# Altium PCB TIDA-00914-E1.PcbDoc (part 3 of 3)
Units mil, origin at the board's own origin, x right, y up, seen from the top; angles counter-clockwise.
Board outline 6575 x 7007.88 mil, 4 copper layers (Top Layer, GND, PWR, Bottom Layer), stack 79.834 mil thick; 302 components, 122 nets, 688 pads, 184 vias.
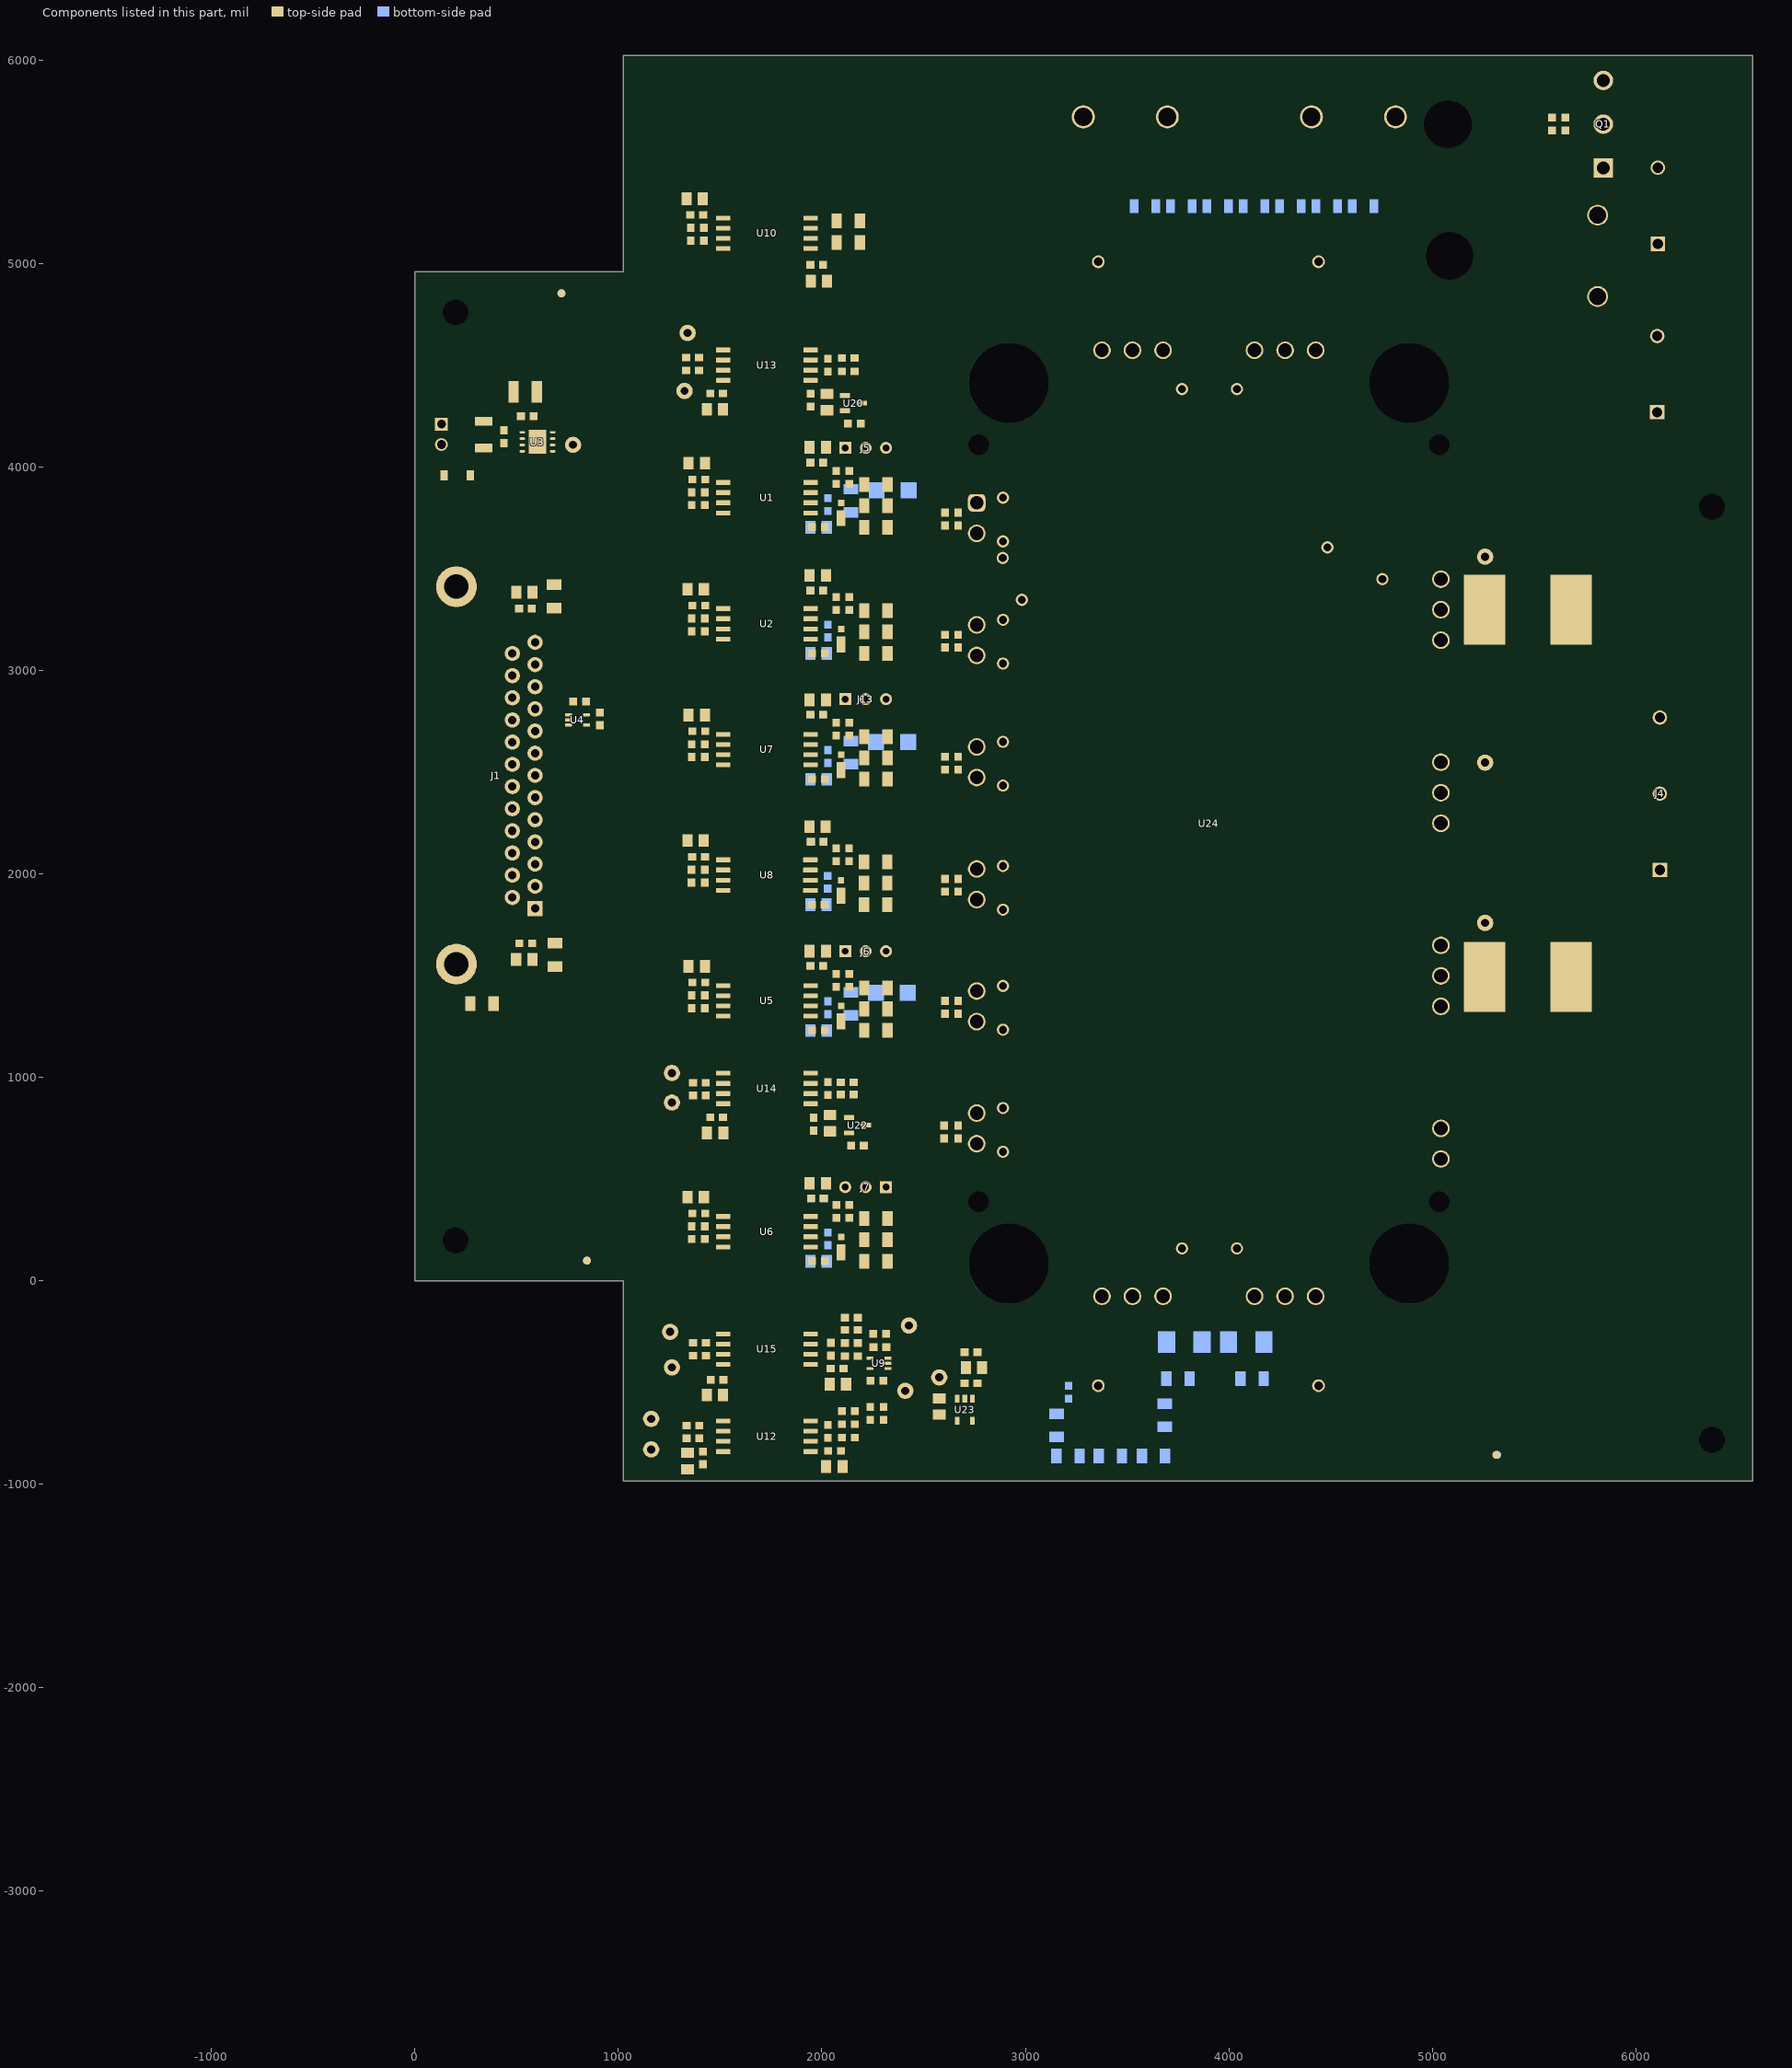
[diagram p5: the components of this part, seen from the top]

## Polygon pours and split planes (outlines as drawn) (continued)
NetC7_1 on Top Layer "NETC7_1_L01_P421" (solid, remove dead copper, pour order 421): 20 vertices, not listed, extent 552,3099 724,3440
GND on Top Layer "GND_L01_P419" (solid, remove dead copper, pour order 419): 523,3360 523,3434 517,3440 422,3440 413,3431 413,3055 425,3043 507,3043 515,3051 523,3059 523,3359
GND on Top Layer "GND_L01_P417" (solid, remove dead copper, pour order 417): 523,1610 523,1536 517,1530 422,1530 413,1539 413,1915 425,1927 507,1927 515,1919 523,1911 523,1611
NetC1_2 on Top Layer "NETC1_2_L01_P415" (solid, remove dead copper, pour order 415): 20 vertices, not listed, extent 552,1530 724,1871
3V3 on Top Layer "3V3_L01_P181" (solid, remove dead copper, pour order 181): 557,4150 557,4435 572,4450 577,4455 607,4455 828,4455 839,4444 839,4055 819,4035 567,4035 557,4045
GND on Top Layer "GND_L01_P179" (solid, remove dead copper, pour order 179): 542,4175 532,4165 62,4165 47,4180 47,4320 57,4330 337,4330 352,4345 352,4440 367,4455 532,4455 542,4445
5V0 on Top Layer "5V0_L01_P177" (solid, remove dead copper, pour order 177): 532,4145 252,4145 237,4130 237,3910 247,3900 532,3900 542,3910 542,4140 537,4145
NetD1_2 on Top Layer "NETD1_2_L01_P175" (solid, remove dead copper, pour order 175): 57,4140 167,4140 177,4130 177,3915 177,3905 172,3900 57,3900 47,3910 47,4130
NetC15_2 on Top Layer "Top Layer-MU" (solid, remove dead copper, pour order 527): 1985,3910 1910,3910 1905,3915 1905,4130 1915,4140 1965,4140 1970,4135 1970,3990 1985,3975 1990,3970 2005,3955 2022,3938 2088,3938 2088,3901 1994,3901
VCC_WT on Top Layer "Top Layer-MU" (solid, remove dead copper, pour order 539): 1907,3786 1907,3628 1913,3622 1986,3622 1990,3626 1990,3649 1973,3666 1973,3743 1985,3755 1985,3782.07 1977.07,3790 1911,3790
NetC12_2 on Top Layer "Top Layer-MU" (solid, remove dead copper, pour order 549): 1985,3290 1910,3290 1905,3295 1905,3495 1910,3500 1965,3500 1970,3495 1970,3365 2017,3318 2088,3318 2088,3281 1994,3281
VCC on Top Layer "Top Layer-MU" (solid, remove dead copper, pour order 553): 1907,3166 1907,3015 1911,3011 1985,3011 1990,3016 1990,3035 1973,3052 1973,3123 1985,3135 1985,3162.07 1977.07,3170 1911,3170
NetC80_2 on Top Layer "Top Layer-MU" (solid, remove dead copper, pour order 561): 1980,4445 1910,4445 1905,4440 1905,4350 1915,4340 2140,4340 2145,4345 2145,4410 2135,4420 2005,4420
VCC_WT on Top Layer "Top Layer-MU" (solid, remove dead copper, pour order 565): 2080,4116 2080,4287 2085,4292 2103,4292 2142,4292 2147,4287 2149,4285 2149,4199 2149,4063 2146,4060 2087,4060 2080,4067
GND_WT on Top Layer "Top Layer-MU" (solid, remove dead copper, pour order 567): 2182,4132 2182,4183 2171,4194 2171,4327 2176,4332 2242,4332 2246,4328 2248,4326 2248,4101 2248,4061 2241,4054 2192,4054 2182,4064
VCC_VT on Top Layer "Top Layer-MU" (solid, remove dead copper, pour order 569): 1907,2547.97 1907,2389.97 1913,2383.97 1986,2383.97 1990,2387.97 1990,2410.97 1973,2427.97 1973,2504.97 1985,2516.97 1985,2544.04 1977.07,2551.97 1911,2551.97
NetC37_2 on Top Layer "Top Layer-MU" (solid, remove dead copper, pour order 573): 1985,2671.97 1910,2671.97 1905,2676.97 1905,2886.97 1909,2890.97 1966,2890.97 1970,2886.97 1970,2751.97 1985,2736.97 1990,2731.97 2005,2716.97 2022,2699.97 2088,2699.97 2088,2662.97 1994,2662.97
VCC on Top Layer "Top Layer-MU" (solid, remove dead copper, pour order 587): 1906,1931 1906,1780 1910,1776 1984,1776 1989,1781 1989,1800 1972,1817 1972,1888 1984,1900 1984,1927.07 1976.07,1935 1910,1935
NetC43_2 on Top Layer "Top Layer-MU" (solid, remove dead copper, pour order 589): 1984,2055 1909,2055 1904,2060 1904,2260 1909,2265 1964,2265 1969,2260 1969,2130 2016,2083 2087,2083 2087,2046 1993,2046
NetC28_2 on Top Layer "Top Layer-MU" (solid, remove dead copper, pour order 597): 1985,302 1910,302 1905,307 1905,507 1910,512 1965,512 1970,507 1970,377 2017,330 2088,330 2088,293 1994,293
VCC on Top Layer "Top Layer-MU" (solid, remove dead copper, pour order 599): 1907,178 1907,27 1911,23 1985,23 1990,28 1990,47 1973,64 1973,135 1985,147 1985,174.07 1977.07,182 1911,182
NetC18_2 on Top Layer "Top Layer-MU" (solid, remove dead copper, pour order 603): 1985,1436.97 1910,1436.97 1905,1441.97 1905,1651.97 1909,1655.97 1966,1655.97 1970,1651.97 1970,1516.97 1985,1501.97 1990,1496.97 2005,1481.97 2022,1464.97 2088,1464.97 2088,1427.97 1994,1427.97
VCC_UT on Top Layer "Top Layer-MU" (solid, remove dead copper, pour order 607): 1907,1312.97 1907,1154.97 1913,1148.97 1986,1148.97 1990,1152.97 1990,1175.97 1973,1192.97 1973,1269.97 1985,1281.97 1985,1309.04 1977.07,1316.97 1911,1316.97
VDC- on Top Layer "Top Layer-MU" (solid, remove dead copper, pour order 623): 29 vertices, not listed, extent 1993,351 2249,518
VDC- on Top Layer "Top Layer-MU" (solid, remove dead copper, pour order 631): 17 vertices, not listed, extent 1991,2107 2170,2266
VDC- on Top Layer "Top Layer-MU" (solid, remove dead copper, pour order 633): 17 vertices, not listed, extent 1992,3342 2171,3501
W_PHASE_REF on Top Layer "Top Layer-MU" (solid, remove dead copper, pour order 689): 5346,3594 5010,3594 4990,3574 4990,3120 5010,3100 5350,3100 5365,3115 5365,3575
NETJ1_26 on Top Layer "NETJ1_26_L01_P799" (solid, remove dead copper, pour order 799): 303,1573 303,1274 295,1266 113,1266 102,1277 102,1637 121,1656 293,1656 303,1646
GND on Top Layer "Top Layer-MU" (solid, remove dead copper, pour order 801): 357,1393 357,1455 364,1462 488,1462 496,1454 496,1274 488,1266 364,1266 357,1273
NetJ4_2 on Top Layer "NETJ4_2_L01_P803" (solid, remove dead copper, pour order 803): 18 vertices, not listed, extent 4989,2199 6205,2614
W_BOT on Top Layer "W_BOT_L01_P817" (solid, remove dead copper, pour order 817): 2281,3321 2281,3060 2298,3043 2349,3043 2394,3043 2497,3146 2504,3153 2577,3153 2908,3153 2943,3188 2943,3299 2905,3337 2355,3337 2297,3337
V_BOT on Top Layer "V_BOT_L01_P823" (solid, remove dead copper, pour order 823): 19 vertices, not listed, extent 2286,1799 2940,2120
U_TOP on Top Layer "U_TOP_L01_P825" (solid, remove dead copper, pour order 825): 18 vertices, not listed, extent 2285,1179 2937,1508
NetD9_2 on Top Layer "Top Layer-MU" (solid, remove dead copper, pour order 884): 17 vertices, not listed, extent 5483,4214 6157,5298
U_BOT on Top Layer "U_BOT_L01_P872" (solid, remove dead copper, pour order 872): 26 vertices, not listed, extent 2290,42 2941,910
GND on Top Layer "Top Layer-MU" (solid, remove dead copper, pour order 948): 18 vertices, not listed, extent 30,-960 1554,6002
VCC_UT on PWR "VCC_UT_L03_P856" (solid, remove dead copper, pour order 856): 18 vertices, not listed, extent 1907,1145 2169,1655
VCC_VT on PWR "VCC_VT_L03_P854" (solid, remove dead copper, pour order 854): 18 vertices, not listed, extent 1907,2384 2169,2894
W_PHASE on PWR "Top Layer-MU" (solid, remove dead copper, pour order 771): 5576,3475 5576,3109 5957,2728 6165,2728 6195,2758 6195,3080 5789,3486 5587,3486
U_PHASE on PWR "Top Layer-MU" (solid, remove dead copper, pour order 759): 5576,1315 5576,1681 5957,2062 6165,2062 6195,2032 6195,1710 5789,1304 5587,1304
3V3_VDC on PWR "3V3_VDC_L03_P441" (solid, remove dead copper, pour order 441): 2085,-154 1921,-154 1909,-166 1909,-927 1928,-946 2817,-946 2846,-917 2846,-171 2829,-154 2086,-154
VCC_WT on PWR "Top Layer-MU" (solid, remove dead copper, pour order 675): 2080,4133 2080,3991 1907,3818 1907,3628 1913,3622 1986,3622 1990,3626 1990,3787 2149,3946 2149,4126 2149,4134 2145,4138 2084,4138 2080,4134
NetJ4_2 on PWR "NETJ4_2_L03_P807" (solid, remove dead copper, pour order 807): 18 vertices, not listed, extent 4989,2199 6205,2614
VDC-_F on PWR "VDC-_F_L03_P912" (solid, remove dead copper, pour order 912): 23 vertices, not listed, extent 4347,5391 6339,6004
VDC- on PWR "VDC-_L03_P928" (solid, remove dead copper, pour order 928): 24 vertices, not listed, extent 2802,-607 3784,5988
W_PHASE_REF on PWR "Top Layer-MU" (solid, remove dead copper, pour order 936): 5339,3601 5017,3601 4990,3574 4990,3120 5010,3100 5350,3100 5365,3115 5365,3575
U_PHASE_REF on PWR "Top Layer-MU" (solid, remove dead copper, pour order 938): 5341,1799 5015,1799 4990,1774 4990,1320 5010,1300 5350,1300 5365,1315 5365,1775
VDC+ on PWR "Top Layer-MU" (solid, remove dead copper, pour order 930): 24 vertices, not listed, extent 4080,-595 6168,5135
5V0 on PWR "5V0_L03_P952" (solid, remove dead copper, pour order 952): 22 vertices, not listed, extent 35,1407 784,4015
3V3 on PWR "Top Layer-MU" (solid, remove dead copper, pour order 956): 18 vertices, not listed, extent 30,-960 1554,6002
VDC- on GND "VDC-_L02_P860" (solid, remove dead copper, pour order 860): 51 vertices, not listed, extent 1909,-966 3250,5385
GND_UT on GND "GND_UT_L02_P831" (solid, remove dead copper, pour order 831): 20 vertices, not listed, extent 1905,648 2810,1655
VCC_UT on GND "VCC_UT_L02_P829" (solid, remove dead copper, pour order 829): 1917,1188 1981,1188 1994,1175 1994,1154 1994,840 2143,691 2143,617 2126,600 1931,600 1913,618 1905,626 1905,1080 1905,1176
U_PHASE_REF on GND "Top Layer-MU" (solid, remove dead copper, pour order 793): 5341,1799 5015,1799 4990,1774 4990,1320 5010,1300 5350,1300 5365,1315 5365,1775
W_PHASE_REF on GND "Top Layer-MU" (solid, remove dead copper, pour order 779): 5339,3601 5017,3601 4990,3574 4990,3120 5010,3100 5350,3100 5365,3115 5365,3575
W_PHASE on GND "Top Layer-MU" (solid, remove dead copper, pour order 769): 5576,3475 5576,3109 5957,2728 6165,2728 6195,2758 6195,3080 5789,3486 5587,3486
U_PHASE on GND "Top Layer-MU" (solid, remove dead copper, pour order 757): 5576,1315 5576,1681 5957,2062 6165,2062 6195,2032 6195,1710 5789,1304 5587,1304
GND_WT on GND "Top Layer-MU" (solid, remove dead copper, pour order 695): 17 vertices, not listed, extent 1905,3600 2820,4610
NetJ4_2 on GND "NETJ4_2_L02_P805" (solid, remove dead copper, pour order 805): 18 vertices, not listed, extent 4989,2199 6205,2614
GND on GND "Top Layer-MU" (solid, remove dead copper, pour order 866): 18 vertices, not listed, extent 30,-960 1554,6002
NetD9_2 on GND "Top Layer-MU" (solid, remove dead copper, pour order 874): 20 vertices, not listed, extent 5619,5180 5899,5740
VDC-_F on GND "VDC-_F_L02_P888" (solid, remove dead copper, pour order 888): 23 vertices, not listed, extent 4347,5391 6339,6004
VDC- on GND "VDC-_L02_P904" (solid, remove dead copper, pour order 904): 24 vertices, not listed, extent 2802,-607 3784,5988
GND_VT on GND "Top Layer-MU" (solid, remove dead copper, pour order 699): 1905,2502 2017,2390 2795,2390 2805,2400 2810,2405 2810,2495 2810,2505 2795,2520 2385,2520 2365,2540 2361,2544 2361,2759 2228,2892 1914,2892 1905,2883
VDC+ on GND "Top Layer-MU" (solid, remove dead copper, pour order 946): 24 vertices, not listed, extent 4080,-595 6168,5135
VCC on Bottom Layer "VCC_L04_P858" (solid, remove dead copper, pour order 858): 23 vertices, not listed, extent 1908,3013 2468,3929
VCC on Bottom Layer "VCC_L04_P840" (solid, remove dead copper, pour order 840): 24 vertices, not listed, extent 1905,1776 2465,2692
VCC on Bottom Layer "VCC_L04_P838" (solid, remove dead copper, pour order 838): 28 vertices, not listed, extent 1904,14 2052,196
W_PHASE on Bottom Layer "Top Layer-MU" (solid, remove dead copper, pour order 773): 5576,3475 5576,3109 5957,2728 6165,2728 6195,2758 6195,3080 5789,3486 5587,3486
U_PHASE on Bottom Layer "Top Layer-MU" (solid, remove dead copper, pour order 761): 5576,1315 5576,1681 5957,2062 6165,2062 6195,2032 6195,1710 5789,1304 5587,1304
VEE on Bottom Layer "Top Layer-MU" (solid, remove dead copper, pour order 651): 1986,391 1986,490 2131,490 2146,475 2146,449 2128,431 2050,431 2050,367 2050,221 2047,218 2012,218 2010,220 2010,367
NetC15_2 on Bottom Layer "Top Layer-MU" (solid, remove dead copper, pour order 531): 1950,4050 1960,4050 1964,4046 1964,3996 1990,3970 1990,3960 1990,3915 1985,3910 1910,3910 1905,3915 1905,4045 1910,4050
VCC_WT on Bottom Layer "Top Layer-MU" (solid, remove dead copper, pour order 541): 2178,3805 1925,3805 1907,3787 1907,3628 1913,3622 1986,3622 1990,3626 1990,3649 1973,3666 1973,3743 1982,3752 2181,3752 2183,3754 2183,3800
NetD14_1 on Bottom Layer "Top Layer-MU" (solid, remove dead copper, pour order 545): 2302.37,3930 2112.37,3930 2106.37,3924 2106.37,3857 2111.37,3852 2114.37,3849 2257.37,3849 2303.37,3849 2305.37,3851 2305.37,3928 2303.37,3930
VEE_WT on Bottom Layer "Top Layer-MU" (solid, remove dead copper, pour order 547): 22 vertices, not listed, extent 1986,3826 2348,4141
NetC12_2 on Bottom Layer "Top Layer-MU" (solid, remove dead copper, pour order 551): 1950,3430 1960,3430 1964,3426 1964,3371 1990,3345 1990,3340 1990,3295 1985,3290 1910,3290 1905,3295 1905,3425 1910,3430
NetD13_1 on Bottom Layer "Top Layer-MU" (solid, remove dead copper, pour order 577): 2302.37,2691.97 2112.37,2691.97 2106.37,2685.97 2106.37,2618.97 2111.37,2613.97 2114.37,2610.97 2257.37,2610.97 2303.37,2610.97 2305.37,2612.97 2305.37,2689.97 2303.37,2691.97
VCC_VT on Bottom Layer "Top Layer-MU" (solid, remove dead copper, pour order 579): 2178,2566.97 1925,2566.97 1907,2548.97 1907,2389.97 1913,2383.97 1986,2383.97 1990,2387.97 1990,2410.97 1973,2427.97 1973,2504.97 1982,2513.97 2181,2513.97 2183,2515.97 2183,2561.97
NetC37_2 on Bottom Layer "Top Layer-MU" (solid, remove dead copper, pour order 581): 1950,2811.97 1960,2811.97 1964,2807.97 1964,2757.97 1990,2731.97 1990,2721.97 1990,2676.97 1985,2671.97 1910,2671.97 1905,2676.97 1905,2806.97 1910,2811.97
NetC43_2 on Bottom Layer "Top Layer-MU" (solid, remove dead copper, pour order 595): 1949,2195 1959,2195 1963,2191 1963,2136 1989,2110 1989,2105 1989,2060 1984,2055 1909,2055 1904,2060 1904,2190 1909,2195
NetC28_2 on Bottom Layer "Top Layer-MU" (solid, remove dead copper, pour order 609): 1950,442 1960,442 1964,438 1964,383 1990,357 1990,352 1990,307 1985,302 1910,302 1905,307 1905,437 1910,442
NetC18_2 on Bottom Layer "Top Layer-MU" (solid, remove dead copper, pour order 615): 1950,1576.97 1960,1576.97 1964,1572.97 1964,1522.97 1990,1496.97 1990,1486.97 1990,1441.97 1985,1436.97 1910,1436.97 1905,1441.97 1905,1571.97 1910,1576.97
VCC_UT on Bottom Layer "Top Layer-MU" (solid, remove dead copper, pour order 617): 2178,1331.97 1925,1331.97 1907,1313.97 1907,1154.97 1913,1148.97 1986,1148.97 1990,1152.97 1990,1175.97 1973,1192.97 1973,1269.97 1982,1278.97 2181,1278.97 2183,1280.97 2183,1326.97
NetD12_1 on Bottom Layer "Top Layer-MU" (solid, remove dead copper, pour order 619): 2302.37,1456.97 2112.37,1456.97 2106.37,1450.97 2106.37,1383.97 2111.37,1378.97 2114.37,1375.97 2257.37,1375.97 2303.37,1375.97 2305.37,1377.97 2305.37,1454.97 2303.37,1456.97
VEE on Bottom Layer "Top Layer-MU" (solid, remove dead copper, pour order 627): 1986,3379 1986,3423 1995,3432 2167,3432 2171,3428 2171,3382 2168,3379 2074,3379 2050,3355 2050,3210.17 2045.83,3206 2012,3206 2010,3208 2010,3355
VEE on Bottom Layer "Top Layer-MU" (solid, remove dead copper, pour order 629): 1985,2144 1985,2188 1994,2197 2196,2197 2202,2191 2202,2150 2196,2144 2073,2144 2049,2120 2049,1975.17 2044.83,1971 2011,1971 2009,1973 2009,2120
NetJ4_2 on Bottom Layer "NETJ4_2_L04_P809" (solid, remove dead copper, pour order 809): 18 vertices, not listed, extent 4989,2199 6205,2614
VEE_VT on Bottom Layer "VEE_VT_L04_P862" (solid, remove dead copper, pour order 862): 31 vertices, not listed, extent 1986,2587.97 2348,2889.97
VEE_UT on Bottom Layer "VEE_UT_L04_P864" (solid, remove dead copper, pour order 864): 31 vertices, not listed, extent 1986,1348.97 2348,1650.97
VDC-_F on Bottom Layer "VDC-_F_L04_P920" (solid, remove dead copper, pour order 920): 23 vertices, not listed, extent 4347,5391 6339,6004
GND on Bottom Layer "Top Layer-MU" (solid, remove dead copper, pour order 926): 18 vertices, not listed, extent 30,-960 1554,6002
VDC- on Bottom Layer "VDC-_L04_P932" (solid, remove dead copper, pour order 932): 27 vertices, not listed, extent 2802,-607 3784,5988
W_PHASE_REF on Bottom Layer "Top Layer-MU" (solid, remove dead copper, pour order 940): 5339,3601 5017,3601 4990,3574 4990,3120 5010,3100 5350,3100 5365,3115 5365,3575
U_PHASE_REF on Bottom Layer "Top Layer-MU" (solid, remove dead copper, pour order 942): 5341,1799 5015,1799 4990,1774 4990,1320 5010,1300 5350,1300 5365,1315 5365,1775
VDC+ on Bottom Layer "VDC+_L04_P944" (solid, remove dead copper, pour order 944): 35 vertices, not listed, extent 4080,-595 6168,5325
VCC on Bottom Layer "VCC_L04_P832" (solid, remove dead copper, pour order 832): 2462,1456 2491,1427 2491,546 2372,427 2287,427 2279,435 2279,486 2400,607 2400,1339 2384,1355 2384,1456

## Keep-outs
Keep-Out Layer:
  circle w10: c2770,4110 r51.18
  circle w10: c5033.78,4110 r51.18
  circle w10: c5033.78,389.53 r51.18
  circle w10: c2770,389.53 r51.18
  circle w10: c4886.14,84.41 r196.85
  circle w10: c2917.64,84.41 r196.85
  circle w10: c2917.64,4415.12 r196.85
  circle w10: c4886.14,4415.12 r196.85
  circle w10: c5078.01,5686 r118.11
  circle w10: c5085.05,5039 r118.11
  text ".Layer_Name" at -798.27,-3325.04 h60

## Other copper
Top Layer:
  text ".layer_Name" at -783.27,-3314.55 h60
GND:
  text "GND" at -715.27,-3310.55 h60
PWR:
  text "PWR" at -705.27,-3310.55 h60
Bottom Layer:
  text ".Layer_Name" at -724.27,-3324.55 h60
Multi-Layer:
  pour cut-out: 1904,-984.25 1554,-984.25 1554,6023.62 1904,6023.62

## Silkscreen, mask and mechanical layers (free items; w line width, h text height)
Top Overlay:
  circle w10: c493,4175 r9.22
  circle w10: c2359,-440 r5.66
  lines w6: 475,3435 475,3521 497,3543 ; 557,1435 595,1473 595,1529 ; 1903,4631 1903,4849 ; 1904,-900 1904,-955 1907,-958 1921,-972 2217,-972 2252,-937 5866,-937 6565,-238 6565,5995 6556,6004 3855,6004 1968,6004 1904,5940 1904,5286 ; 1904,-633 1904,-544 ; 1904,-207 1904,4 ; 1904,540 1904,643 ; 1904,1066 1904,1152 ; 1904,1674 1904,1763 ; 1904,2288 1904,2373 ; 1904,2912 1904,2997 ; 1904,3524 1904,3622 ; 1916,4243 1926,4253 1976,4253 ; 1985,-461 2003,-443 2007,-443 ; 2005,-253 2005,-263.1 2017.47,-275.57 ; 2029,4212 2029,4236 ; 2074,-263 2074,-138 2358,-138 2358,-168 2358,-341 ; 2137,2165 2137,2191 2156,2210 ; 2162.2,401.98 2180.98,401.98 ; 2162.2,4009.98 2173.98,4009.98 ; 2166,3380 2178,3380 ; 2168,1524 2185,1524 ; 2168,2760 2185,2760 ; 2197,-659 2201,-663 2201,-677.71 2201,-724 2207,-730 2207,-794 2219,-806 2248,-806 ; 2244,-806 2292,-806 ; 2246,-715 2258,-727 2326,-727 ; 2308,-128 2308,-86 2345,-49 ; 2329,-49 2345,-49 ; 2336,-360 2352,-360 2358,-354 2358,-326 ; 2345,-64 2345,-49 ; 2380,-81 2626,-81 2626,118 2380,118 2380,-81
  lines w10: -1667.27,-3396.72 4932.73,-3396.72 ; -1667.27,-3193.38 4934.73,-3193.38 ; -1667.27,-2990.05 -1667.27,-3600.05 2337.73,-3600.05 4934.73,-3600.05 ; -1666.77,-3600.05 -1666.77,-2990.05 4934.73,-2990.05 ; 83,3869 83,4026 ; 815.73,-3598.55 815.73,-2988.55 ; 3024.73,-3194.88 3024.73,-2991.55 ; 3698.73,-3600.38 3698.73,-3397.55 ; 4934.23,-3600.05 4934.23,-2990.05
  text "Fuse" at 3965,5926 h60
  text "1000Vdc" at 3963,5873 h60
  text "565V DC" at 6295,5830 h60
  text "30A" at 3965,5818 h60
  text "22A DC" at 6328,5776 h60
  text "VDC-" at 6044,5703 h50
  text "VDC+" at 5713,4992 h50
  text "BRAKE+" at 5596,4613 h50
  text "GND" at 93,4298 h50 r90
  text "BRAKE-" at 5591,4239 h50
  text "+5V" at 99,3717 h50 r90
  text "0.3A" at 176,3707 h50 r90
  text "400V AC" at 6266,3249 h60
  text "22A AC" at 6301,3198 h60
  text "W_PHASE" at 6074,3043 h50
  text "V_PHASE" at 5864,2268 h50 r90
  text "U_PHASE" at 6059,1727 h50
  text "+15V" at 2357,527 h50 r90
  text "0.1A" at 2430,526 h50 r90
  text "TIDA-00914-E1" at 5182,-416 h80
  text "UL 94 V-0" at 5814,-716 h60
  text ".layer_Name" at -757.27,-3312.55 h60
Bottom Overlay:
  lines w10: 5718,4775 5718.44,4774.56
  text ".Layer_Name" at -798.27,-3325.04 h60
Top Paste:
  text ".Layer_Name" at -810.27,-3328.04 h60
Bottom Paste:
  text ".Layer_Name" at -810.27,-3328.04 h60
Top Solder:
  text ".Layer_Name" at -782.27,-3335.55 h60
Bottom Solder:
  text ".Layer_Name" at -735.27,-3331.55 h60
M1 Board Outline:
  the board outline again, w20
M2 Board Dimensions:
  rectangle: -1430.5,-2771 -1055.5,-2646
  rectangle: -1555.5,-2646 -1430.5,-2521
  lines w7: -1555.5,-2646 -555.5,-2646 ; -1430.5,-2771 -1430.5,-2521 ; -1305.5,-2771 -1305.5,-2521 ; -1055.5,-2771 -1055.5,-2521 ; -805.5,-2771 -805.5,-2521 ; -1555.5,-2771 -1555.5,-2521 -555.5,-2521 -555.5,-2771 -1555.5,-2771
  lines w10: -1555.5,-2836 -1555.5,-2816 ; -1495.5,-2846 -1555.5,-2826 ; -1495.5,-2806 -1555.5,-2826 ; -1331.42,-2826 -1555.5,-2826 ; -779.58,-2826 -555.5,-2826 ; -615.5,-2846 -555.5,-2826 ; -615.5,-2806 -555.5,-2826 ; -555.5,-2836 -555.5,-2816
  text "1000 (mil)" at -1321.42,-2861.99 h60
M3 3D STEP Top:
  text ".Layer_Name" at -798.27,-3325.04 h60
M4 3D STEP Bottom:
  text ".Layer_Name" at -798.27,-3325.04 h60
M5 Assembly Top:
  circle w10: c2116,2861 r19.92
  circle w10: c2113,4095 r16.12
  circle w10: c2113,4355 r9.85
  circle w10: c737,2784 r6.71
  circle w10: c2115,1694 r8
  circle w10: c2770,-575 r11.18
  circle w10: c646,1824 r10.63
  circle w6: c2341,-438 r8
  circle w6: c2385,463 r8
  circle w6: c2134,803 r8
  circle w10: c6103,4889 r9.85
  circle w10: c6117,4061 r9.22
  circle w10: c5895,2027 r11.4
  circle w10: c200,200 r128
  circle w10: c6375,-780 r128
  circle w10: c6375,3805 r128
  circle w10: c200,4760.63 r128
  lines w6: -1667.27,-3192.55 4936.73,-3192.55 ; -1665.77,-3396.55 4938.73,-3396.55 ; 815.73,-3598.05 815.73,-2990.55 ; 1352.73,-3192.55 1352.73,-2990.05 ; 2064.73,-3189.88 2064.73,-2989.55 ; 2463.73,-3597.55 2463.73,-2990.05 ; 3024.73,-3189.55 3024.73,-2990.55 ; 4936.23,-3596.05 4936.23,-2990.05 -1666.27,-2990.05 -1666.27,-3598.55 4938.73,-3598.55 ; 6066.23,-2990.05 6068.73,-2992.55 ; 2087,4256 2087,4375 2182,4375 2182,4256 2087,4256 ; 2100,708 2100,825 2255,825 2255,779 2255,708 2234,708 2100,708
  text "H2" at 171,4747 h35
  text "H3" at 6362,3793 h35
  text "H1" at 167,184 h35
  text "H4" at 6349,-796 h35
  text "COMPONENTS MARKED 'DNP' SHOULD NOT BE POPULATED." at -221.77,-2785.05 h30
  text "ASSEMBLY VARIANT:" at -222.27,-2900.55 h30
  text ".VariantName" at 813.73,-2900.55 h30
  text "ALL ARTWORK VIEWED FROM TOP SIDE" at -1603.77,-3122.22 h30
  text "BOARD #:" at 872.73,-3122.22 h30
  text ".PRJ_Number" at 1418.23,-3122.22 h30
  text "REV:" at 2262.73,-3122.22 h30
  text ".PCB_Rev" at 2554.23,-3122.22 h30
  text "SVN REV:" at 3100.73,-3122.22 h30
  text ".VersionControl_RevNumber" at 3606.73,-3122.22 h30
  text ".layer_Name" at -840.27,-3304.55 h30
  text ".PRJ_Number" at 1263.23,-3307.22 h30
  text "LAYER NAME =" at -1610.27,-3311.55 h30
  text "TID #:" at 887.73,-3312.22 h30
  text ".plot_File_Name" at -1612.27,-3500.55 h30
  text "GENERATED    :" at 874.73,-3530.88 h30
  text ".Print_Date" at 1744.23,-3530.88 h30
  text ".Print_Time" at 2473.23,-3530.88 h30
  text "TEXAS INSTRUMENTS" at 3737.73,-3530.88 h30
M6 Assembly Bottom:
  circle w10: c5832,4748 r24.02
  circle w10: c5809,5412 r23.35
  lines w6: -1667.77,-3193.88 4934.23,-3193.88 ; -1665.77,-3397.22 4934.23,-3397.22 ; 470.73,-3193.38 470.73,-2990.05 ; 929.23,-3600.55 -1667.77,-3600.55 -1667.77,-2990.55 4933.73,-2990.55 ; 929.23,-3600.05 4934.23,-3600.05 ; 1352.73,-3194.88 1352.73,-2991.55 ; 2463.73,-3600.55 2463.73,-2990.55 ; 3359.23,-3600.05 4934.73,-3600.05 ; 4934.23,-3600.55 4934.23,-2990.55 4934.23,-3600.55
  text "D9" at 5797,5031 h30 r270
  text "COMPONENTS MARKED 'DNP' SHOULD NOT BE POPULATED." at 4726.73,-2784.55 h30
  text ".VariantName" at 3682.73,-2900.55 h30
  text "ASSEMBLY VARIANT:" at 4721.73,-2900.55 h30
  text "SVN REV:" at 166.23,-3122.72 h30
  text ".PCB_Rev" at 712.73,-3122.72 h30
  text "REV:" at 1004.23,-3122.72 h30
  text ".PRJ_Number" at 1848.73,-3122.72 h30
  text "BOARD #:" at 2394.23,-3122.72 h30
  text "PCB VIEWED FROM BOTTOM SIDE" at 4870.73,-3122.72 h30
  text "Not in versioncontrol" at -175,-3125 h30
  text "LAYER NAME =" at 4865.73,-3307.55 h30
  text ".Layer_Name" at 4092.73,-3314.55 h30
  text "IGNORE ->" at 1172.58,-3325.04 h30
  text ".Print_Time" at 793.73,-3531.38 h30
  text ".Print_Date" at 1522.73,-3531.38 h30
  text "GENERATED    :" at 2392.23,-3531.38 h30
  text ".plot_File_Name" at 4065.23,-3531.38 h30
  text "PLOT NAME =" at 4870.73,-3531.38 h30
M9 Title Sheet:
  drawing of 57 lines, arcs and shapes, not listed
  text "4" at 6861.24,10334.95 h70
  text "5" at 9360.23,10334.95 h70
  text "1" at -590.27,10329.45 h70
  text "2" at 1814.73,10324.45 h70
  text "3" at 4339.73,10324.45 h70
  text "6" at 11729.73,10324.45 h70
  text "A" at -1791.77,4426.95 h70
  text "A" at 13008.23,4426.95 h70
  text "B" at -1791.77,2046.95 h70
  text "B" at 13008.23,2046.95 h70
  text "C" at -1791.77,-328.05 h70
  text "C" at 13008.23,-328.05 h70
  text "PROJECT TITLE:" at 9968.23,-2189.05 h45
  text ".PRJ_Title" at 10179,-2310 h65
  text "DESIGNED FOR:" at 9968.23,-2490.05 h45
  text ".PRJ_Customer" at 10018.23,-2630.05 h70
  text "D" at -1791.77,-2698.05 h70
  text "D" at 13008.23,-2698.05 h70
  text "FILE NAME:" at 9968.23,-2790.05 h45
  text ".PCB_File_Name_No_Path" at 10299.73,-2915.55 h70
  text "Texas Instruments (TI) and/or its licensors do not warrant the accuracy or completeness of this specification" at 4998.73,-3071.89 h45
  text "ENGINEER:" at 9968.23,-3080.05 h45
  text "LAYOUT BY:" at 11473.23,-3080.05 h45
  text "or any information contained therein. TI and/or its licensors do not warrant that this design will meet" at 4953.75,-3184.55 h45
  text ".PRJ_Engineer" at 10217.23,-3209.55 h40
  text ".PCB_Layout" at 11722.73,-3209.55 h40
  text "the specifications, will be suitable for your application or fit for any particular purpose, or will operate in" at 4953.75,-3297.22 h45
  text "ALTIUM DESIGNER VERSION:" at 11473.23,-3390.05 h45
  text "an implementation. TI and/or its licensors do not warrant that the design is production worthy. You should" at 4953.75,-3409.88 h45
  text "completely validate and test your design implementation to confirm the system functionality for your application." at 4998.73,-3522.55 h45
  text ".print_Scale" at 10018.23,-3523.38 h70
  text ".Application_BuildNumber" at 11523.73,-3523.38 h70
  text "2" at 1860.23,-3730.05 h70
  text "3" at 4349.58,-3730.05 h70
  text "4" at 6856.24,-3730.05 h70
  text "5" at 9355.23,-3730.05 h70
  text "6" at 11860.23,-3730.05 h70
M10 Fab Notes:
  drawing of 226 lines, arcs and shapes, not listed
  text "DESIGN INFORMATION" at 11005.75,4343.45 h60
  text "(REFER ALSO ARRAY/PANEL PROFILING INFORMATION)" at 10644.19,4181.74 h60
  text "BOARD SIZE" at 9958.19,4177.45 h60
  text "167MM" at 10420.51,4049.63 h60
  text "X" at 10926.19,4049.63 h60
  text "178MM" at 11157.51,4049.63 h60
  text "Number of Layers :" at 10361.19,3852.45 h60
  text "4" at 11456,3842.45 h60
  text "MIN. TRACK WIDTH:" at 10361.19,3713.45 h60
  text "15" at 11457.43,3713.45 h60
  text "MIL" at 11612.19,3713.45 h60
  text "8" at 11459.73,3589.45 h60
  text "MIN. CLEARANCE:" at 10361.19,3581.45 h60
  text "MIL" at 11612.19,3581.45 h60
  text "MIN. VIA DRILL SIZE:" at 10361.19,3449.45 h60
  text "MIL" at 11612.19,3449.45 h60
  text "7.87" at 11364,3448 h60
  text "5.91 MIL" at 11056.19,3325.74 h60
  text "MINIMUM ANNULAR RING" at 10031.96,3321.46 h60
  text "EXTERNAL" at 11764.19,3321.46 h60
  text "PER" at 10243,3220 h60
  text "IPC-D-275 CLASS 2 LEVEL C" at 10446,3218 h60
  text "MIL, HOLES" at 11933.19,3131.16 h60
  text "+/-" at 11540.73,3130.45 h60
  text "+/-" at 12394.73,3130.45 h60
  text "REGISTRATION TOLERANCES:" at 10024.96,3125.45 h60
  text "METAL" at 11224.73,3125.45 h60
  text "5" at 11800.93,3125.45 h60
  text "3" at 12633.93,3125.45 h60
  text "MIL" at 12750.19,3125.45 h60
  text "HOLE SIZE TOLERANCE (UNLESS OTHERWISE SPECIFIED): +/- 3 MIL" at 10027.96,3041.45 h60
  text "MATERIAL:" at 9957.19,2857.99 h60
  text "FR-4 High Tg" at 10943.64,2717.66 h60
  text "FR-408" at 10378.19,2709.09 h60
  text "X" at 10784.73,2709.45 h60
  text "OTHER" at 11866.19,2709.09 h60
  text "63 MIL (1.6mm) +/-10%" at 10698.3,2546.37 h60
  text "THICKNESS:" at 10031.96,2542.09 h60
  text "X" at 10570.13,2542.09 h60
  text "OTHER" at 11983.19,2542.09 h60
  text "TOLERANCE:" at 10031.96,2384.09 h60
  text "X" at 10871.27,2384.09 h60
  text "ANSI IPC-6012 TYPE 3 CLASS 2" at 11058.21,2384.09 h60
  text "OTHER +/-" at 11058.19,2228.09 h60
  text "BOW & TWIST:" at 10031.96,2071.09 h60
  text "X" at 10871.27,2071.09 h60
  text "ANSI IPC-6012 TYPE 3 CLASS 2" at 11058.21,2071.09 h60
  text "OTHER +/-" at 11058.19,1912.58 h60
  text "COPPER THICKNESS (FINISHED):" at 9957.19,1777.09 h60
  text "1.4MIL (1oz)" at 10837.19,1624.37 h60
  text "2MIL (1.4oz)" at 11604.19,1624.37 h60
  text "2.8MIL (2oz)" at 12331.19,1624.37 h60
  text "OUTER:" at 10314.19,1620.09 h60
  text "X" at 10701.73,1616.45 h60
  text "X" at 10708.73,1474.45 h60
  text "1.4MIL (1oz)" at 10837.19,1467.37 h60
  text "2.8MIL (2oz)" at 11604.19,1467.37 h60
  text "N/A" at 12330.73,1467.74 h60
  text "INNER SIGNAL:" at 10025.11,1463.09 h60
  text "DRILLING:" at 9957.19,1324.09 h60
  text "REFERENCE:" at 10031.96,1207.09 h60
  text "X" at 10680.19,1207.09 h60
  text "AS SHOWN" at 10867.19,1207.09 h60
  text "X" at 11581.19,1207.09 h60
  text "NC_DRILL FILES" at 11718.19,1207.09 h60
  text "PTH MIN COPPER THICKNESS:" at 10031.96,1049.09 h60
  text "X" at 11382.19,1049.09 h60
  text "1MIL" at 11519.19,1049.09 h60
  text "OTHER" at 12016.19,1049.09 h60
  text "BOARD FINISH:" at 9957.19,890.09 h60
  text "SILKSCREEN:" at 10112.41,772.09 h60
  text "X" at 11061.19,772.09 h60
  text "TOP" at 11187.19,772.09 h60
  text "X" at 11571.19,772.09 h60
  text "BOTTOM" at 11698.19,772.09 h60
  text "SILKSCREEN COLOR:" at 10112.41,605.09 h60
  text "X" at 11060.15,605.09 h60
  text "WHITE" at 11187.19,605.09 h60
  text "OTHER" at 11698.19,605.09 h60
  text "SOLDER RESIST COLOR:" at 10112.41,435.09 h60
  text "X" at 10680.16,275.89 h60
  text "GREEN" at 10807.19,275.89 h60
  text "BLUE" at 11398.19,275.89 h60
  text "OTHER" at 11936.19,275.89 h60
  text "IMMERSION GOLD (ENIG)" at 11018.19,87.37 h60
  text "X" at 10831.25,86.09 h60
  text "ENEPIG" at 12355.73,84.09 h60
  text "SURFACE FINISH:" at 9957.19,83.09 h60
  text "IMM. TIN/SILVER OR EQUIV" at 10286.73,-73.91 h60
  text "OTHER" at 11718.19,-73.91 h60
  text "ARRAY/PANEL:" at 9957.19,-252.91 h60
  text "CUT AND TRIM PER MECH LAYER 1" at 11018.19,-257.2 h60
  text "N.C. ROUTE" at 11018.19,-408.91 h60
  text "X" at 11697.19,-408.91 h60
  text "V. SCORE" at 11884.19,-408.91 h60
  text "CERTIFICATION:" at 9957.19,-545.91 h60
  text "MATERIALS AND WORKMANSHIP FOR ALL PCBS" at 10682.19,-545.91 h60
  text "TO MEET OR EXCEED THE REQUIREMENTS OF:" at 10682.19,-643.91 h60
  text "X" at 10308.7,-780.41 h60
  text "ANSI IPC-A-600F CLASS ->" at 10447.7,-780.41 h60
  text "X" at 12086.75,-780.41 h60
  text "2" at 12205.7,-780.41 h60
  text "1" at 11890.7,-781.91 h60
  text "3" at 12559.7,-781.91 h60
  text "X" at 10310.75,-939.91 h60
  text "UL 94V-0" at 10447.7,-939.91 h60
  text "X" at 11122.75,-939.91 h60
  text "RoHS" at 11259.7,-939.91 h60
  text "OTHER" at 11904.1,-939.91 h60
  text "PER ORDER" at 12301.16,-939.91 h60
  text "VIA TENTING:" at 11174.73,-1073.55 h60
  text "X" at 12254.73,-1075.55 h60
  text "ADDITIONAL REQUIREMENTS:" at 9957.19,-1080.91 h60
  text "YES" at 11724.4,-1082.63 h60
  text "NO" at 12089.21,-1087.86 h60
  text "MICROSECTION:" at 10031.96,-1195.91 h60
  text "YES" at 10937.7,-1195.91 h60
  text "IMPEDANCE CONTROL:" at 11196.73,-1202.55 h60
  text "YES" at 12180.73,-1203.55 h60
  text "X" at 12722.73,-1210.55 h60
  text "NO" at 12556.21,-1220.86 h60
  text "REQUIRED" at 11799.19,-1352.05 h60
  text "BARE BOARD ELEC. TEST:" at 10031.96,-1354.91 h60
  text "NONE" at 11337.7,-1354.91 h60
  text "X" at 11672.19,-1354.91 h60
  text "PER ORDER" at 12391.19,-1354.91 h60
  text "MANUFACTURER'S UL:" at 10031.96,-1511.91 h60
  text "RAIL" at 11197.7,-1516.2 h60
  text "METAL" at 11689.51,-1516.2 h60
  text "X" at 12064.73,-1516.55 h60
  text "SILK" at 12201.19,-1516.2 h60
M11 Gerber Information:
  lines w10: -1668.27,-3600.05 2336.73,-3600.05 ; -1667.27,-3600.05 -1667.27,-2990.05 ; -1667.27,-3396.72 4932.73,-3396.72 ; -1667.27,-3193.38 4934.73,-3193.38 ; -1666.77,-3600.05 -1666.77,-2990.05 4934.73,-2990.05 4934.73,-3600.05 2337.73,-3600.05 ; 815.73,-3598.55 815.73,-2988.55 ; 3698.73,-3600.38 3698.73,-3397.55 ; 3024.73,-3194.88 3024.73,-2991.55 3024.73,-3194.88
  text "BOARD #:" at 872.73,-3122.22 h60
  text ".PRJ_Number" at 1418.23,-3122.22 h60
  text "REV:" at 2262.73,-3122.22 h60
  text ".PCB_Rev" at 2554.23,-3122.22 h60
  text "SVN REV:" at 3100.73,-3122.22 h60
  text ".VersionControl_RevNumber" at 3606.73,-3122.22 h60
  text "ALL ARTWORK VIEWED FROM TOP SIDE" at -1604.77,-3128.22 h60
  text "LAYER NAME =" at -1606.27,-3311.55 h60
  text "TID #:" at 877.73,-3317.22 h60
  text ".PRJ_Number" at 1243.23,-3317.22 h60
  text ".plot_File_Name" at -1614.27,-3510.55 h60
  text "GENERATED    :" at 874.73,-3530.88 h60
  text ".Print_Date" at 1744.23,-3530.88 h60
  text ".Print_Time" at 2473.23,-3530.88 h60
  text "TEXAS INSTRUMENTS" at 3737.73,-3530.88 h60
M12 Stackup:
  lines w6: 9984.73,4993.45 12534.73,4993.45 ; 9984.73,5097.85 12534.73,5097.85 ; 9924.73,4508.45 ccw(c9958.73,4508.45) 9958.73,4474.45 12560.73,4474.45 ccw(c12560.73,4508.45) 12594.73,4508.45 12594.73,5214.45 ccw(c12560.73,5214.45) 12560.73,5248.45 9958.73,5248.45 ccw(c9958.73,5214.45) 9924.73,5214.45 9924.73,4508.45
  text "Layer Stack Up Detail for: TIDA-00914-E1" at 9984.73,5130.55 h57
  text "Layer" at 9984.73,5058.85 h24
  text "Gerber" at 10880.55,5058.85 h24
  text "Copper" at 11444.07,5058.85 h24
  text "Dielectric" at 12046.77,5058.85 h24
  text "Name" at 9984.73,5010.85 h24
  text "Document" at 10880.55,5010.85 h24
  text "Thickness" at 11444.07,5010.85 h24
  text "Material" at 12046.77,5010.85 h24
  text "Top Solder Mask" at 9999.73,4919.45 h34
  text "(.GTS)" at 10880.55,4917.89 h34
  text "Solder Resist" at 12046.77,4917.89 h34
  text "Top Layer" at 9994.73,4824.45 h34
  text "(.GTL)" at 10880.55,4821.14 h34
  text "1.4mil" at 11444.07,4821.14 h34
  text "FR4-High Tg" at 12075.73,4820.45 h34
  text "FR4-High Tg" at 12080.73,4765.45 h34
  text "1.4mil" at 11444.07,4756.14 h34
  text "GND" at 9993.73,4752.45 h34
  text "(.G1)" at 10879.55,4744.14 h34
  text "FR4-High Tg" at 12080.73,4690.45 h34
  text "1.4mil" at 11444.07,4686.14 h34
  text "(.G2)" at 10879.55,4674.14 h34
  text "PWR" at 9993.73,4672.45 h34
  text "FR4-High Tg" at 12080.73,4595.45 h34
  text "Bottom Layer" at 9989.73,4594.45 h34
  text "(.GBL)" at 10888.73,4590.45 h34
  text "1.4mil" at 11448.73,4584.45 h34
  text "Solder Resist" at 12040.73,4517.45 h34
  text "(.GBS)" at 10885.73,4510.45 h34
  text "Bottom Solder Mask" at 9994.73,4509.45 h34
M13 Component Bodies Top:
  text ".Layer_Name" at -798.27,-3325.04 h60
M14 Component Bodies Bottom:
  text ".Layer_Name" at -798.27,-3325.04 h60
M15 Courtyards Top:
  text ".Layer_Name" at -798.27,-3325.04 h60
M16 Courtyards Bottom:
  text ".Layer_Name" at -798.27,-3325.04 h60
Drill Drawing:
  circle w10: c2311.62,8048.83 r20
  circle w10: c2311.62,8048.83 r33.33
  circle w10: c2311.62,7898.83 r33.33
  lines w10: 2278.29,7598.83 2311.62,7565.5 2344.96,7598.83 2311.62,7632.17 2278.29,7598.83 ; 2278.29,7715.5 2344.96,7715.5 2344.96,7782.17 2278.29,7782.17 2278.29,7715.5 ; 2278.29,8232.17 2344.96,8232.17 2311.62,8165.5 2278.29,8232.17 ; 2278.29,8315.5 2311.62,8332.17 2344.96,8315.5 2328.29,8348.83 2344.96,8382.17 2311.62,8365.5 2278.29,8382.17 2294.96,8348.83 2278.29,8315.5 ; 2278.29,8782.17 2294.96,8782.17 2311.62,8765.5 2328.29,8782.17 2344.96,8782.17 2328.29,8798.83 2344.96,8815.5 2328.29,8815.5 2311.62,8832.17 2294.96,8815.5 2278.29,8815.5 2294.96,8798.83 2278.29,8782.17 ; 2278.29,8915.5 2278.29,8932.17 2294.96,8948.83 2278.29,8965.5 2278.29,8982.17 2294.96,8982.17 2311.62,8965.5 2328.29,8982.17 2344.96,8982.17 2344.96,8965.5 2328.29,8948.83 2344.96,8932.17 2344.96,8915.5 2328.29,8915.5 2311.62,8932.17 2294.96,8915.5 2278.29,8915.5 ; 2278.29,9082.17 2294.96,9082.17 2311.62,9065.5 2328.29,9082.17 2344.96,9082.17 2328.29,9098.83 2344.96,9115.5 2328.29,9115.5 2311.62,9132.17 2294.96,9115.5 2278.29,9115.5 2294.96,9098.83 2278.29,9082.17 ; 2278.29,9215.5 2278.29,9232.17 2294.96,9248.83 2278.29,9265.5 2278.29,9282.17 2294.96,9282.17 2311.62,9265.5 2328.29,9282.17 2344.96,9282.17 2344.96,9265.5 2328.29,9248.83 2344.96,9232.17 2344.96,9215.5 2328.29,9215.5 2311.62,9232.17 2294.96,9215.5 2278.29,9215.5 ; 2278.29,9432.17 2344.96,9432.17 2311.62,9365.5 2278.29,9432.17 ; 2278.29,9515.5 2344.96,9515.5 2344.96,9582.17 2278.29,9582.17 2278.29,9515.5 ; 2291.62,7728.83 2331.62,7728.83 2331.62,7768.83 2291.62,7768.83 2291.62,7728.83 ; 2291.62,8218.83 2331.62,8218.83 2311.62,8178.83 2291.62,8218.83 ; 2291.62,8328.83 2311.62,8338.83 2331.62,8328.83 2321.62,8348.83 2331.62,8368.83 2311.62,8358.83 2291.62,8368.83 2301.62,8348.83 2291.62,8328.83 ; 2291.62,8788.83 2301.62,8788.83 2311.62,8778.83 2321.62,8788.83 2331.62,8788.83 2321.62,8798.83 2331.62,8808.83 2321.62,8808.83 2311.62,8818.83 2301.62,8808.83 2291.62,8808.83 2301.62,8798.83 2291.62,8788.83 ; 2291.62,9228.83 2291.62,9238.83 2301.62,9248.83 2291.62,9258.83 2291.62,9268.83 2301.62,9268.83 2311.62,9258.83 2321.62,9268.83 2331.62,9268.83 2331.62,9258.83 2321.62,9248.83 2331.62,9238.83 2331.62,9228.83 2321.62,9228.83 2311.62,9238.83 2301.62,9228.83 2291.62,9228.83
  lines w15: 2218.5,7370.5 6097.47,7370.5 ; 2218.5,9770.5 6097.47,9770.5 ; 2769.38,7220.5 2769.38,9920.5 ; 3467.19,7220.5 3467.19,9920.5 ; 4812.79,7220.5 4812.79,9920.5 ; 5318.67,7220.5 5318.67,9920.5 ; 2218.5,7220.5 6097.47,7220.5 6097.47,9920.5 2218.5,9920.5 2218.5,7220.5
  text "Symbol" at 2308.5,9815.5 h72
  text "Hit Count" at 2814.38,9815.5 h72
  text "Finished Hole Size" at 3512.19,9815.5 h72
  text "Plated" at 4857.79,9815.5 h72
  text "Hole Type" at 5363.67,9815.5 h72
  text "2" at 2814.38,9665.5 h60
  text "82.68mil (2.100mm)" at 3512.19,9665.5 h60
  text "PTH" at 4857.79,9665.5 h60
  text "Round" at 5363.67,9665.5 h60
  text "A" at 2279.41,9655.51 h66.67
  text "2" at 2814.38,9515.5 h60
  text "120.00mil (3.048mm)" at 3512.19,9515.5 h60
  text "PTH" at 4857.79,9515.5 h60
  text "Round" at 5363.67,9515.5 h60
  text "2" at 2814.38,9365.5 h60
  text "236.22mil (6.000mm)" at 3512.19,9365.5 h60
  text "NPTH" at 4857.79,9365.5 h60
  text "Round" at 5363.67,9365.5 h60
  text "3" at 2814.38,9215.5 h60
  text "62.00mil (1.575mm)" at 3512.19,9215.5 h60
  text "PTH" at 4857.79,9215.5 h60
  text "Round" at 5363.67,9215.5 h60
  text "4" at 2814.38,9065.5 h60
  text "88.58mil (2.250mm)" at 3512.19,9065.5 h60
  text "PTH" at 4857.79,9065.5 h60
  text "Round" at 5363.67,9065.5 h60
  text "4" at 2814.38,8915.5 h60
  text "102.36mil (2.600mm)" at 3512.19,8915.5 h60
  text "NPTH" at 4857.79,8915.5 h60
  text "Round" at 5363.67,8915.5 h60
  text "4" at 2814.38,8765.5 h60
  text "128.00mil (3.251mm)" at 3512.19,8765.5 h60
  text "NPTH" at 4857.79,8765.5 h60
  text "Round" at 5363.67,8765.5 h60
  text "4" at 2814.38,8615.5 h60
  text "393.70mil (10.000mm)" at 3512.19,8615.5 h60
  text "NPTH" at 4857.79,8615.5 h60
  text "Round" at 5363.67,8615.5 h60
  text "B" at 2279.41,8605.51 h66.67
  text "5" at 2814.38,8465.5 h60
  text "7.87mil (0.200mm)" at 3512.19,8465.5 h60
  text "PTH" at 4857.79,8465.5 h60
  text "Round" at 5363.67,8465.5 h60
  text "D" at 2279.41,8455.51 h66.67
  text "6" at 2814.38,8315.5 h60
  text "43.31mil (1.100mm)" at 3512.19,8315.5 h60
  text "PTH" at 4857.79,8315.5 h60
  text "Round" at 5363.67,8315.5 h60
  text "7" at 2814.38,8165.5 h60
  text "51.18mil (1.300mm)" at 3512.19,8165.5 h60
  text "PTH" at 4857.79,8165.5 h60
  text "Round" at 5363.67,8165.5 h60
  text "12" at 2814.38,8015.5 h60
  text "33.47mil (0.850mm)" at 3512.19,8015.5 h60
  text "PTH" at 4857.79,8015.5 h60
  text "Round" at 5363.67,8015.5 h60
  text "25" at 2814.38,7865.5 h60
  text "41.00mil (1.041mm)" at 3512.19,7865.5 h60
  text "PTH" at 4857.79,7865.5 h60
  text "Round" at 5363.67,7865.5 h60
  text "35" at 2814.38,7715.5 h60
  text "40.00mil (1.016mm)" at 3512.19,7715.5 h60
  text "PTH" at 4857.79,7715.5 h60
  text "Round" at 5363.67,7715.5 h60
  text "35" at 2814.38,7565.5 h60
  text "66.93mil (1.700mm)" at 3512.19,7565.5 h60
  text "PTH" at 4857.79,7565.5 h60
  text "Round" at 5363.67,7565.5 h60
  text "179" at 2814.38,7415.5 h60
  text "16.00mil (0.406mm)" at 3512.19,7415.5 h60
  text "PTH" at 4857.79,7415.5 h60
  text "Round" at 5363.67,7415.5 h60
  text "C" at 2279.41,7405.51 h66.67
  text "329 Total" at 2814.38,7265.5 h60
  text "Drill Table" at 6073,6981 h60
  text "FOR 7.87MIL DRILL +0/-7.87MIL" at 6070,6867 h60
  text "FOR 16MIL DRILL +0/-16MIL" at 6073,6769 h60
  text "FOR PTH DRILL +/-3MIL" at 6068.73,6677.45 h60
  text "FOR NPTH DRILL +/-2MIL" at 6073,6594 h60
  text ".layer_Name" at -693.27,-3308.55 h60

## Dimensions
1024.73,6023.62 to 1024.73,4960.63 on M2 Board Dimensions
1024.73,6023.62 to 6575,6023.62 on M2 Board Dimensions
6575,-984.25 to 6575,6023.62 on M2 Board Dimensions
0,0 to 6575,-984.25 on M2 Board Dimensions
0,0 to 1024.73,0 on M2 Board Dimensions
0,4960.63 to 0,0 on M2 Board Dimensions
